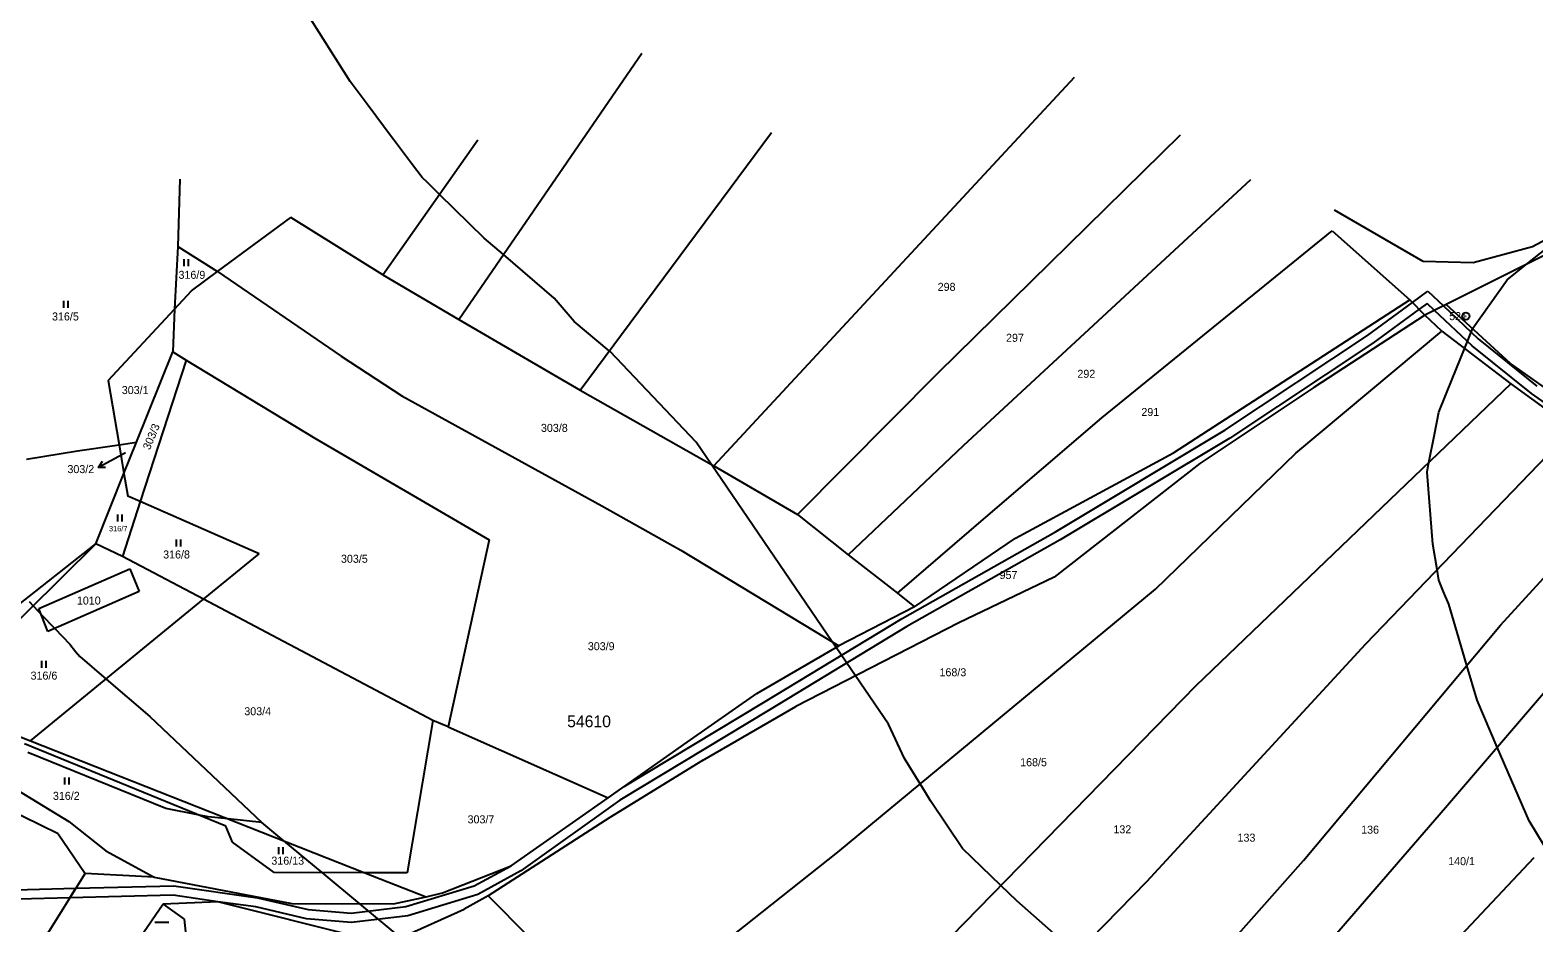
# Model space of a CAD drawing. Extents: x -749173 to -746119, y -1132678 to -1130338.
# Drawn here: x -747690.2 to -747370.7, y -1130860.8 to -1130671.2 of the extents above; entities that cross this region are included whole.
import ezdxf

# ---------------------------------------------------------------- set-up
doc = ezdxf.new("R2010")
doc.units = 0
for name, color, linetype in [('Vrstva 1', 7, 'Continuous'), ('Vrstva 16', 7, 'Continuous'), ('Vrstva 17', 7, 'Continuous'), ('Vrstva 18', 7, 'Continuous'), ('Vrstva 24', 7, 'Continuous'), ('Vrstva 25', 7, 'Continuous'), ('Vrstva 30', 7, 'Continuous'), ('Vrstva 52', 7, 'Continuous'), ('Vrstva 53', 7, 'Continuous'), ('Vrstva 6', 7, 'Continuous')]:
    doc.layers.add(name, color=color, linetype=linetype)

msp = doc.modelspace()

# ---------------------------------------------------------------- linework, layer by layer
at = {"layer": 'Vrstva 1'}
for points in [[(-747394.22, -1130720.39), (-747413.11, -1130709.47)], [(-747347.62, -1130708.71), (-747389.39, -1130729.51)], [(-747353.84, -1130708.05), (-747371.05, -1130717.26)], [(-747650.43, -1130722.5), (-747634.84, -1130710.99)], [(-747413.6, -1130713.86), (-747397.12, -1130728.52)], [(-747371.05, -1130717.26), (-747383.63, -1130720.64)], [(-747383.63, -1130720.64), (-747394.22, -1130720.39)], [(-747655.93, -1130726.56), (-747650.43, -1130722.5)], [(-747659.58, -1130730.48), (-747655.93, -1130726.56)], [(-747447.29, -1130761.01), (-747397.12, -1130728.52)], [(-747397.12, -1130728.52), (-747393.87, -1130731.74)], [(-747673.66, -1130745.6), (-747659.58, -1130730.48)], [(-747393.87, -1130731.74), (-747417.46, -1130747.1)], [(-747389.39, -1130729.51), (-747393.87, -1130731.74)], [(-747673.66, -1130745.6), (-747671.35, -1130759.26)], [(-747417.46, -1130747.1), (-747441.69, -1130763.28)], [(-747671.35, -1130759.26), (-747670.31, -1130765.39)], [(-747480.85, -1130779.08), (-747447.29, -1130761.01)], [(-747441.69, -1130763.28), (-747472.69, -1130787.42)], [(-747670.31, -1130765.39), (-747669.5, -1130770.18)], [(-747666.84, -1130771.35), (-747669.5, -1130770.18)], [(-747641.57, -1130782.42), (-747666.84, -1130771.35)], [(-747502.34, -1130793.69), (-747480.85, -1130779.08)], [(-747653.39, -1130792.09), (-747641.57, -1130782.42)], [(-747688.36, -1130794.01), (-747669.08, -1130785.64)], [(-747669.08, -1130785.64), (-747667.06, -1130790.44)], [(-747472.69, -1130787.42), (-747492.89, -1130797.06)], [(-747690.17, -1130822.16), (-747653.39, -1130792.09)], [(-747667.06, -1130790.44), (-747686.45, -1130798.94)], [(-747686.45, -1130798.94), (-747688.36, -1130794.01)], [(-747502.34, -1130793.69), (-747518.4, -1130801.96)], [(-747492.89, -1130797.06), (-747527.53, -1130814.88)], [(-747535.86, -1130812.1), (-747518.4, -1130801.96)], [(-747715.36, -1130812.23), (-747690.17, -1130822.16)], [(-747550.62, -1130822.39), (-747535.86, -1130812.1)], [(-747547.35, -1130826.32), (-747527.53, -1130814.88)], [(-747690.17, -1130822.16), (-747619.1, -1130850.16)], [(-747567.45, -1130834.27), (-747550.62, -1130822.39)], [(-747547.35, -1130826.32), (-747567.07, -1130838.41)], [(-747692.92, -1130832.64), (-747682.03, -1130839.3)], [(-747684.28, -1130841.87), (-747695.55, -1130836.35)], [(-747588.01, -1130848.67), (-747567.45, -1130834.27)], [(-747682.03, -1130839.3), (-747674.17, -1130845.51)], [(-747567.07, -1130838.41), (-747592.89, -1130855.02)], [(-747684.28, -1130841.87), (-747678.53, -1130850.34)], [(-747674.17, -1130845.51), (-747663.88, -1130851.09)], [(-747619.1, -1130850.16), (-747606.08, -1130855.29)], [(-747602.62, -1130854.39), (-747588.01, -1130848.67)], [(-747687.14, -1130864.03), (-747678.53, -1130850.34)], [(-747663.88, -1130851.09), (-747678.53, -1130850.34)], [(-747663.88, -1130851.09), (-747634.6, -1130856.66)], [(-747650.32, -1130856.36), (-747662, -1130856.84)], [(-747620.11, -1130863.87), (-747650.32, -1130856.36)], [(-747613, -1130856.77), (-747606.08, -1130855.29)], [(-747606.08, -1130855.29), (-747602.62, -1130854.39)], [(-747592.89, -1130855.02), (-747598.03, -1130857.85)], [(-747592.89, -1130855.02), (-747566.95, -1130881.22)], [(-747662, -1130856.84), (-747666.96, -1130864.06)], [(-747634.6, -1130856.66), (-747613, -1130856.77)], [(-747613.42, -1130864.85), (-747598.03, -1130857.85)]]:
    msp.add_lwpolyline(points, dxfattribs=at)
at = {"layer": 'Vrstva 16'}
msp.add_line((-747674.19, -1130764.11), (-747675.69, -1130764.07), dxfattribs=at)
for points in [[(-747672.16, -1130762.18), (-747675.69, -1130764.07), (-747674.89, -1130762.79)], [(-747670, -1130761.02), (-747672.16, -1130762.18)]]:
    msp.add_lwpolyline(points, dxfattribs=at)
at = {"layer": 'Vrstva 24'}
msp.add_line((-747385.23, -1130731.96), (-747385.13, -1130731.96), dxfattribs=at)
msp.add_circle((-747385.18, -1130731.96), 0.756, dxfattribs=at)
at = {"layer": 'Vrstva 25'}
for p, q in [((-747657.6, -1130719.87), (-747657.6, -1130721.37)), ((-747656.6, -1130721.37), (-747656.6, -1130719.87)), ((-747683.14, -1130728.68), (-747683.14, -1130730.18)), ((-747682.14, -1130730.18), (-747682.14, -1130728.68)), ((-747671.67, -1130774.06), (-747671.67, -1130775.56)), ((-747670.67, -1130775.56), (-747670.67, -1130774.06)), ((-747659.24, -1130779.4), (-747659.24, -1130780.9)), ((-747658.24, -1130780.9), (-747658.24, -1130779.4)), ((-747687.85, -1130805.12), (-747687.85, -1130806.62)), ((-747686.85, -1130806.62), (-747686.85, -1130805.12)), ((-747682.92, -1130829.93), (-747682.92, -1130831.43)), ((-747681.92, -1130831.43), (-747681.92, -1130829.93)), ((-747637.48, -1130844.73), (-747637.48, -1130846.23)), ((-747636.48, -1130846.23), (-747636.48, -1130844.73)), ((-747663.77, -1130860.61), (-747660.77, -1130860.61))]:
    msp.add_line(p, q, dxfattribs=at)
at = {"layer": 'Vrstva 30'}
for p, q in [((-747396.55, -1130729.08), (-747393.28, -1130726.69)), ((-747393.28, -1130726.69), (-747389.97, -1130729.8)), ((-747406.11, -1130736.08), (-747396.55, -1130729.08)), ((-747395.11, -1130730.51), (-747404.97, -1130737.72)), ((-747393.44, -1130729.29), (-747395.11, -1130730.51)), ((-747391.88, -1130730.75), (-747393.44, -1130729.29)), ((-747383.87, -1130738.28), (-747391.88, -1130730.75)), ((-747389.97, -1130729.8), (-747382.55, -1130736.76)), ((-747436.4, -1130756.15), (-747406.11, -1130736.08)), ((-747404.97, -1130737.72), (-747435.34, -1130757.85)), ((-747371.27, -1130748.41), (-747383.87, -1130738.28)), ((-747382.55, -1130736.76), (-747370.07, -1130746.81)), ((-747346.12, -1130765.83), (-747371.27, -1130748.41)), ((-747472.39, -1130777.77), (-747436.4, -1130756.15)), ((-747435.34, -1130757.85), (-747471.39, -1130779.49)), ((-747504.97, -1130796.13), (-747472.39, -1130777.77)), ((-747471.39, -1130779.49), (-747503.95, -1130797.85)), ((-747534.38, -1130814.01), (-747504.97, -1130796.13)), ((-747503.95, -1130797.85), (-747533.34, -1130815.73)), ((-747564.03, -1130831.86), (-747534.38, -1130814.01)), ((-747533.34, -1130815.73), (-747564.92, -1130834.73)), ((-747567.45, -1130834.27), (-747564.03, -1130831.86)), ((-747588.01, -1130848.67), (-747567.45, -1130834.27)), ((-747564.92, -1130834.73), (-747585.98, -1130849.72)), ((-747595.88, -1130852.91), (-747588.01, -1130848.67)), ((-747585.98, -1130849.72), (-747595.1, -1130854.77)), ((-747680.49, -1130853.45), (-747659.69, -1130852.9)), ((-747659.69, -1130852.9), (-747641.95, -1130855.46)), ((-747610.43, -1130857.31), (-747595.88, -1130852.91)), ((-747659.81, -1130854.9), (-747681.77, -1130855.49)), ((-747650.32, -1130856.36), (-747659.81, -1130854.9)), ((-747642.31, -1130857.42), (-747650.32, -1130856.36)), ((-747641.95, -1130855.46), (-747631.16, -1130857.93)), ((-747595.1, -1130854.77), (-747610.01, -1130859.27)), ((-747631.48, -1130859.91), (-747642.31, -1130857.42)), ((-747631.16, -1130857.93), (-747622, -1130858.72)), ((-747622, -1130858.72), (-747610.43, -1130857.31)), ((-747610.01, -1130859.27), (-747621.96, -1130860.74)), ((-747621.96, -1130860.74), (-747631.48, -1130859.91))]:
    msp.add_line(p, q, dxfattribs=at)
for points in [[(-747751.71, -1130841.81), (-747745.66, -1130841.56), (-747738.19, -1130843.29), (-747717.5, -1130854.46), (-747712.56, -1130854.9), (-747703.65, -1130854.07), (-747680.49, -1130853.45), (-747681.77, -1130855.49), (-747703.53, -1130856.07), (-747712.56, -1130856.9), (-747718.08, -1130856.42), (-747738.91, -1130845.17), (-747745.84, -1130843.58), (-747751.58, -1130843.84), (-747751.71, -1130841.81)], [(-747681.77, -1130855.49), (-747680.49, -1130853.45)]]:
    msp.add_lwpolyline(points, dxfattribs=at)
at = {"layer": 'Vrstva 52'}
for points in [[(-747467.9, -1130867.28), (-747480.62, -1130856.12), (-747483.99, -1130852.87), (-747492.12, -1130845), (-747498.94, -1130834.87), (-747500, -1130833.13), (-747501.12, -1130831.3), (-747504.44, -1130825.87), (-747507.87, -1130818.62), (-747514.87, -1130808.36), (-747519, -1130802.31), (-747519.82, -1130801.1), (-747545.52, -1130763.4), (-747548.69, -1130758.75), (-747567, -1130739.5), (-747567.2, -1130739.33), (-747574.62, -1130733.12), (-747578.87, -1130728.12), (-747589.65, -1130718.88), (-747593.75, -1130715.37), (-747603.24, -1130706.1), (-747605.81, -1130703.6), (-747606.94, -1130702.5), (-747609.2, -1130699.52), (-747612.83, -1130694.73), (-747613.04, -1130694.46), (-747614.62, -1130692.37), (-747615.17, -1130691.64), (-747618.44, -1130687.25), (-747622.25, -1130682.12), (-747636.75, -1130659.12)], [(-747368.46, -1130844.51), (-747371.75, -1130839.12), (-747378.5, -1130823.48), (-747382.81, -1130813.5), (-747384.98, -1130806.15), (-747387.04, -1130799.14), (-747388.81, -1130793.12), (-747389.91, -1130790.47), (-747390.94, -1130788), (-747391.3, -1130785.79), (-747392.19, -1130780.37), (-747393.44, -1130765.12), (-747393.25, -1130764.19), (-747393.02, -1130763.02), (-747391.86, -1130757.07), (-747390.94, -1130752.37), (-747388.07, -1130745.32), (-747385.46, -1130738.88), (-747383.76, -1130734.67), (-747383.69, -1130734.5), (-747376.44, -1130724.25), (-747372.36, -1130721.03), (-747364.56, -1130714.87)], [(-747690.45, -1130792.58), (-747689.62, -1130793.46), (-747688.51, -1130794.61), (-747687.86, -1130795.29), (-747684.99, -1130798.3), (-747681.81, -1130801.62), (-747680.58, -1130803.14), (-747679.69, -1130804.25), (-747674.11, -1130809.03), (-747664.81, -1130817), (-747641, -1130839.5)], [(-747641, -1130839.5), (-747648.14, -1130838.72), (-747652.44, -1130838.25), (-747654.59, -1130837.83), (-747661.37, -1130836.5), (-747690.75, -1130824.62)], [(-747636.31, -1130843.38), (-747641, -1130839.5)], [(-747611.45, -1130863.95), (-747620.18, -1130856.73), (-747628.15, -1130850.13), (-747636.31, -1130843.38)]]:
    msp.add_lwpolyline(points, dxfattribs=at)
at = {"layer": 'Vrstva 6'}
for points in [[(-747599.16, -1130732.71), (-747560.26, -1130676.14)], [(-747544.95, -1130763.72), (-747468.33, -1130681.23)], [(-747573.4, -1130747.66), (-747532.69, -1130692.96)], [(-747497.27, -1130744), (-747445.84, -1130693.47)], [(-747615.28, -1130723.21), (-747595.09, -1130694.52)], [(-747658.46, -1130702.88), (-747658.86, -1130717.16)], [(-747491.91, -1130759.43), (-747430.87, -1130702.94)], [(-747615.28, -1130723.21), (-747634.84, -1130710.99)], [(-747462.56, -1130753.54), (-747413.6, -1130713.86)], [(-747658.86, -1130717.16), (-747659.58, -1130730.48)], [(-747658.86, -1130717.16), (-747650.43, -1130722.5)], [(-747650.43, -1130722.5), (-747624.13, -1130740.43)], [(-747615.28, -1130723.21), (-747599.16, -1130732.71)], [(-747659.58, -1130730.48), (-747659.94, -1130739.54)], [(-747390.31, -1130735.18), (-747393.87, -1130731.74)], [(-747375.72, -1130742.04), (-747389.39, -1130729.51)], [(-747599.16, -1130732.71), (-747573.4, -1130747.66)], [(-747421.34, -1130761.04), (-747390.31, -1130735.18)], [(-747390.31, -1130735.18), (-747375.64, -1130746.37)], [(-747667.62, -1130758.69), (-747659.94, -1130739.54)], [(-747657.09, -1130741.32), (-747666.84, -1130771.35)], [(-747659.94, -1130739.54), (-747657.09, -1130741.32)], [(-747657.09, -1130741.32), (-747629.73, -1130757.9)], [(-747624.13, -1130740.43), (-747611.24, -1130748.86)], [(-747527.2, -1130774.05), (-747497.27, -1130744)], [(-747344.46, -1130764.04), (-747375.72, -1130742.04)], [(-747573.4, -1130747.66), (-747544.95, -1130763.72)], [(-747375.64, -1130746.37), (-747442.58, -1130810.47)], [(-747375.64, -1130746.37), (-747362.47, -1130755.89)], [(-747611.24, -1130748.86), (-747568.75, -1130772.25)], [(-747487.66, -1130775.09), (-747462.56, -1130753.54)], [(-747362.47, -1130755.89), (-747406.54, -1130801.59)], [(-747691.02, -1130762.3), (-747680.2, -1130760.55)], [(-747680.2, -1130760.55), (-747671.35, -1130759.26)], [(-747671.35, -1130759.26), (-747667.62, -1130758.69)], [(-747670.31, -1130765.39), (-747667.62, -1130758.69)], [(-747629.73, -1130757.9), (-747592.67, -1130779.43)], [(-747516.43, -1130782.61), (-747491.91, -1130759.43)], [(-747544.95, -1130763.72), (-747527.2, -1130774.05)], [(-747451.1, -1130789.94), (-747421.34, -1130761.04)], [(-747676.24, -1130780.32), (-747670.31, -1130765.39)], [(-747377.79, -1130797.57), (-747349.46, -1130766.63)], [(-747666.84, -1130771.35), (-747670.62, -1130783)], [(-747568.75, -1130772.25), (-747551.99, -1130781.63)], [(-747527.2, -1130774.05), (-747516.43, -1130782.61)], [(-747505.92, -1130790.81), (-747487.66, -1130775.09)], [(-747389.53, -1130836.33), (-747337.16, -1130775.31)], [(-747592.67, -1130779.43), (-747601.44, -1130819.19)], [(-747697.97, -1130801.66), (-747676.24, -1130780.32)], [(-747694.06, -1130794.29), (-747676.24, -1130780.32)], [(-747670.62, -1130783), (-747676.24, -1130780.32)], [(-747653.39, -1130792.09), (-747670.62, -1130783)], [(-747551.99, -1130781.63), (-747518.4, -1130801.96)], [(-747516.43, -1130782.61), (-747505.92, -1130790.81)], [(-747604.68, -1130817.79), (-747653.39, -1130792.09)], [(-747518.65, -1130845.8), (-747451.1, -1130789.94)], [(-747505.92, -1130790.81), (-747502.34, -1130793.69)], [(-747419.65, -1130847.56), (-747377.79, -1130797.57)], [(-747406.54, -1130801.59), (-747453.02, -1130852.06)], [(-747442.58, -1130810.47), (-747503.21, -1130872.55)], [(-747604.68, -1130817.79), (-747610.15, -1130850.19)], [(-747601.44, -1130819.19), (-747604.68, -1130817.79)], [(-747601.44, -1130819.19), (-747567.45, -1130834.27)], [(-747648.62, -1130840.27), (-747691.42, -1130822.76)], [(-747452.04, -1130908.53), (-747389.53, -1130836.33)], [(-747647.23, -1130843.67), (-747648.62, -1130840.27)], [(-747638.4, -1130850.1), (-747647.23, -1130843.67)], [(-747540.53, -1130863.15), (-747518.65, -1130845.8)], [(-747370.72, -1130846.96), (-747398.68, -1130876.61)], [(-747619.1, -1130850.16), (-747638.4, -1130850.1)], [(-747610.15, -1130850.19), (-747619.1, -1130850.16)], [(-747464.43, -1130898), (-747419.65, -1130847.56)], [(-747453.02, -1130852.06), (-747509.43, -1130909.76)], [(-747662, -1130856.84), (-747657.53, -1130859.98)], [(-747657.53, -1130859.98), (-747657.11, -1130864.01)]]:
    msp.add_lwpolyline(points, dxfattribs=at)

# ---------------------------------------------------------------- texts
at = {"layer": 'Vrstva 16'}
msp.add_text('303/2', height=1.7, dxfattribs=at).set_placement((-747682.31, -1130765.29))
at = {"layer": 'Vrstva 17'}
msp.add_text('521', height=1.7, dxfattribs=at).set_placement((-747388.74, -1130732.81))
at = {"layer": 'Vrstva 18'}
for s, height, p in [('316/9', 1.7, (-747658.71, -1130724.04)), ('298', 1.7, (-747497.41, -1130726.59)), ('316/5', 1.7, (-747685.58, -1130732.88)), ('297', 1.7, (-747482.88, -1130737.41)), ('292', 1.7, (-747467.72, -1130745.05)), ('303/1', 1.7, (-747670.76, -1130748.51)), ('291', 1.7, (-747454.13, -1130753.17)), ('303/8', 1.7, (-747581.7, -1130756.54)), ('316/7', 1.14, (-747673.48, -1130777.65)), ('316/8', 1.7, (-747661.97, -1130783.42)), ('303/5', 1.7, (-747624.19, -1130784.33)), ('957', 1.7, (-747484.26, -1130787.78)), ('1010', 1.7, (-747680.3, -1130793.2)), ('303/9', 1.7, (-747571.74, -1130802.9)), ('316/6', 1.7, (-747690.14, -1130809.14)), ('168/3', 1.7, (-747497.02, -1130808.43)), ('303/4', 1.7, (-747644.73, -1130816.71)), ('168/5', 1.7, (-747479.88, -1130827.53)), ('316/2', 1.7, (-747685.39, -1130834.67)), ('303/7', 1.7, (-747597.29, -1130839.66)), ('132', 1.7, (-747460.07, -1130841.78)), ('136', 1.7, (-747407.43, -1130841.85)), ('133', 1.7, (-747433.7, -1130843.55)), ('316/13', 1.7, (-747638.98, -1130848.44)), ('140/1', 1.7, (-747388.94, -1130848.54))]:
    msp.add_text(s, height=height, dxfattribs=at).set_placement(p)
for s, height, rotation, p in [('303/3', 1.7, 67.4077, (-747664.81, -1130760.5)), ('303/2', 0.1, 68.9625, (-747670, -1130761.02))]:
    msp.add_text(s, height=height, rotation=rotation, dxfattribs=at).set_placement(p)
at = {"layer": 'Vrstva 53'}
msp.add_text('54610', height=2.5, dxfattribs=at).set_placement((-747576.13, -1130819.25))

doc.saveas('drawing.dxf')
